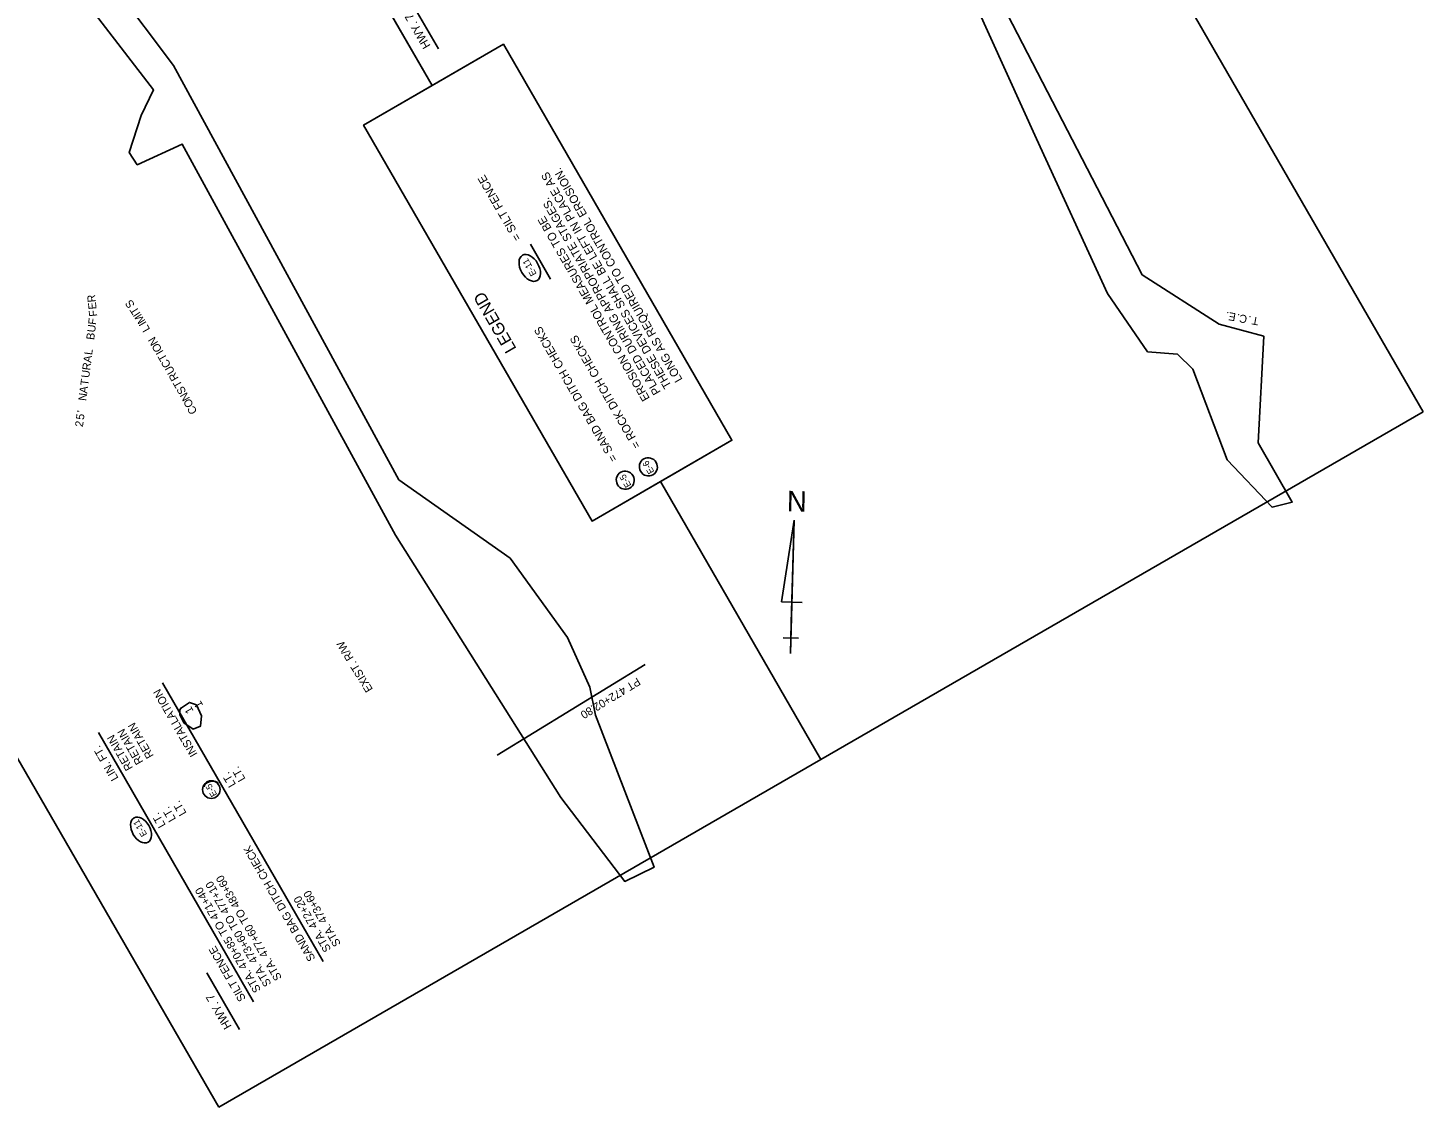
# Model space of a CAD drawing. Extents: x 956270 to 957915, y 1920520 to 1922423.
# Drawn here: x 956869 to 957915, y 1920520 to 1921329 of the extents above; entities that cross this region are included whole.
import ezdxf

# ---------------------------------------------------------------- set-up
doc = ezdxf.new("R2010")
doc.units = 0
for name, color, linetype in [('1', 7, 'Continuous'), ('44', 7, 'Continuous'), ('63', 7, 'Continuous'), ('Level 1', 7, 'Continuous'), ('Level 44', 7, 'Continuous'), ('NO PLOT', 7, 'Continuous'), ('R_Draft', 7, 'Continuous'), ('R_Horz Alg Annot', 7, 'Continuous'), ('S_TREE', 7, 'Continuous')]:
    doc.layers.add(name, color=color, linetype=linetype)

msp = doc.modelspace()

# ---------------------------------------------------------------- linework, layer by layer
at = {"layer": '1'}
for p, q in [((957172.3, 1921286.1), (957029.2, 1921533.9)), ((957225.7, 1921317), (957120.9, 1921256.4)), ((957292.2, 1920959.7), (957120.9, 1921256.4)), ((957367.7, 1921003.2), (957292.2, 1920959.7)), ((957463.8, 1920781), (957343.6, 1920989.3))]:
    msp.add_line(p, q, dxfattribs=at)
msp.add_lwpolyline([(957367.7, 1921003.2), (957397.1, 1921020.2), (957225.7, 1921317)], dxfattribs=at)
msp.add_circle((957006.8, 1920758.4), 6.61, dxfattribs=at)
msp.add_ellipse((956954.1, 1920728.1), major_axis=(-5.26, 9.11), ratio=0.638788, dxfattribs=at)
at = {"layer": '44'}
for p, q in [((957177, 1921313.6), (957152.6, 1921355.9)), ((957090.6, 1920629.6), (956970.1, 1920838.3)), ((957038.5, 1920599.4), (956922.1, 1920801.1)), ((957027.9, 1920578.7), (957003.5, 1920621))]:
    msp.add_line(p, q, dxfattribs=at)
at = {"layer": '63'}
for p, q in [((957443.6, 1920960.4), (957434.3, 1920899.1)), ((957440.9, 1920860.4), (957443.6, 1920960.4)), ((957443.6, 1920960.4), (957441.5, 1920883.5)), ((957434.3, 1920899.1), (957449.6, 1920898.7)), ((957440.9, 1920860.4), (957441.5, 1920883.5)), ((957441.2, 1920872), (957435.5, 1920872.1)), ((957435.5, 1920872.1), (957447, 1920871.8)), ((957440.9, 1920860.4), (957441.2, 1920872))]:
    msp.add_line(p, q, dxfattribs=at)
at = {"layer": 'Level 1'}
for centre, major_axis, ratio in [((957245.5, 1921149.4), (-5.48, 9.49), 0.622952), ((957334.4, 1921000.3), (3.44, -5.96), 0.97521), ((957317.1, 1920990.3), (3.44, -5.96), 0.97521)]:
    msp.add_ellipse(centre, major_axis=major_axis, ratio=ratio, dxfattribs=at)
at = {"layer": 'Level 44'}
msp.add_lwpolyline([(957261.1, 1921141), (957246, 1921167.1)], dxfattribs=at)
at = {"layer": 'NO PLOT'}
for points in [[(957915.2, 1921041.6), (957117.5, 1922423.2), (956666.2, 1922162.6), (956816.7, 1921902), (956875.1, 1921935.7), (957087.6, 1921567.7), (957029.2, 1921533.9), (957172.3, 1921286.1), (957225.7, 1921317), (957397.1, 1921020.2), (957343.6, 1920989.3), (957463.8, 1920781)], [(957915.2, 1921041.6), (957117.5, 1922423.2), (956666.2, 1922162.6), (956816.7, 1921902), (956875.1, 1921935.7), (957087.6, 1921567.7), (957029.2, 1921533.9), (957172.3, 1921286.1), (957225.7, 1921317), (957397.1, 1921020.2), (957343.6, 1920989.3), (957463.8, 1920781)], [(957915.2, 1921041.6), (957117.5, 1922423.2), (956666.2, 1922162.6), (956816.7, 1921902), (956875.1, 1921935.7), (957087.6, 1921567.7), (957029.2, 1921533.9), (957172.3, 1921286.1), (957225.7, 1921317), (957397.1, 1921020.2), (957343.6, 1920989.3), (957463.8, 1920781)], [(957915.2, 1921041.6), (957117.5, 1922423.2), (956666.2, 1922162.6), (956816.7, 1921902), (956875.1, 1921935.7), (957087.6, 1921567.7), (957029.2, 1921533.9), (957172.3, 1921286.1), (957225.7, 1921317), (957397.1, 1921020.2), (957343.6, 1920989.3), (957463.8, 1920781)], [(957012.5, 1920520.4), (956420.5, 1921545.9), (956463.3, 1921570.6), (956365.4, 1921740.1), (956378, 1921747.4), (956270.3, 1921934.1), (956666.2, 1922162.6), (956816.7, 1921902), (956750, 1921863.5), (956962.5, 1921495.4), (957029.2, 1921533.9), (957172.3, 1921286.1), (957120.9, 1921256.4), (957292.2, 1920959.7), (957343.6, 1920989.3), (957463.8, 1920781)], [(957012.5, 1920520.4), (956420.5, 1921545.9), (956463.3, 1921570.6), (956365.4, 1921740.1), (956378, 1921747.4), (956270.3, 1921934.1), (956666.2, 1922162.6), (956816.7, 1921902), (956750, 1921863.5), (956962.5, 1921495.4), (957029.2, 1921533.9), (957172.3, 1921286.1), (957120.9, 1921256.4), (957292.2, 1920959.7), (957343.6, 1920989.3), (957463.8, 1920781)], [(957012.5, 1920520.4), (956420.5, 1921545.9), (956463.3, 1921570.6), (956365.4, 1921740.1), (956378, 1921747.4), (956270.3, 1921934.1), (956666.2, 1922162.6), (956816.7, 1921902), (956750, 1921863.5), (956962.5, 1921495.4), (957029.2, 1921533.9), (957172.3, 1921286.1), (957120.9, 1921256.4), (957292.2, 1920959.7), (957343.6, 1920989.3), (957463.8, 1920781)], [(957012.5, 1920520.4), (956420.5, 1921545.9), (956463.3, 1921570.6), (956365.4, 1921740.1), (956378, 1921747.4), (956270.3, 1921934.1), (956666.2, 1922162.6), (956816.7, 1921902), (956750, 1921863.5), (956962.5, 1921495.4), (957029.2, 1921533.9), (957172.3, 1921286.1), (957120.9, 1921256.4), (957292.2, 1920959.7), (957343.6, 1920989.3), (957463.8, 1920781)]]:
    msp.add_lwpolyline(points, close=True, dxfattribs=at)
for points in [[(956883.9, 1921386.2), (956963.4, 1921282.8), (956954.1, 1921263.6), (956945.3, 1921236), (956951.3, 1921226.7), (956985, 1921242.2), (957144.9, 1920949.1), (957268.7, 1920752.5), (957316.7, 1920689.6), (957338.7, 1920700.2), (957294.8, 1920814.2), (957290.6, 1920835.1), (957273.8, 1920872.4), (957230.9, 1920931.8), (957147.3, 1920990.6), (956978.4, 1921301), (956892, 1921416.3)], [(957580.2, 1921345.8), (957625.4, 1921246.1), (957678.5, 1921130.2), (957708.7, 1921086.5), (957731, 1921084.7), (957742.6, 1921073.5), (957768.3, 1921005.6), (957802, 1920970), (957817.1, 1920973.9), (957791.5, 1921018.4), (957795.7, 1921098.2), (957762.4, 1921107.2), (957704.5, 1921144.2), (957596.2, 1921354.1)]]:
    msp.add_lwpolyline(points, dxfattribs=at)
at = {"layer": 'R_Horz Alg Annot'}
msp.add_lwpolyline([(957221.1, 1920784.2), (957332, 1920852.1)], dxfattribs=at)
at = {"layer": 'S_TREE'}
msp.add_lwpolyline([(956983.6, 1920819.1), (956990.4, 1920823.8), (956995.6, 1920821.9), (956999.3, 1920813.6), (956998.7, 1920806), (956993.3, 1920803.8), (956986.3, 1920808.5), (956983.3, 1920814.5), (956983.3, 1920818.2), (956984.2, 1920819.6)], dxfattribs=at)
msp.add_ellipse((957006.6, 1920761.7), major_axis=(-5.2, -1.23), ratio=0.540699, start_param=3.141593, end_param=6.283185, dxfattribs=at)

# ---------------------------------------------------------------- texts
at = {"layer": '1'}
for s, p in [('E-5 ', (957011.3, 1920754.7)), ('E-11', (956958.8, 1920724.8))]:
    msp.add_text(s, height=4.8, rotation=120, dxfattribs=at).set_placement(p)
at = {"layer": '44'}
for s, height, p in [('HWY. 7', 6.25, (957171.3, 1921315.9)), ('INSTALLATION', 6, (956996.6, 1920785)), ('1', 6, (956993.7, 1920817.4)), ('1', 6, (957000.9, 1920821.6)), ('RETAIN', 6, (956963.8, 1920783.8)), ('RETAIN', 6, (956948.2, 1920774.7)), ('RETAIN', 6, (956955.9, 1920779.2)), ('LIN. FT.', 6, (956937.4, 1920767)), ('LT.', 6, (957032.6, 1920766.4)), ('LT.', 6, (957025.4, 1920762.2)), ('LT.', 6, (956980.5, 1920736.3)), ('LT.', 6, (956988.4, 1920740.8)), ('LT.', 6, (956972.8, 1920731.8)), ('SAND BAG DITCH CHECK', 6, (957085, 1920631.8)), ('STA. 477+60 TO 483+60', 6, (957059.9, 1920617.3)), ('STA. 470+85 TO 471+40', 6, (957044.2, 1920608.3)), ('STA. 473+60 TO 477+10', 6, (957052, 1920612.8)), ('STA. 473+60', 6, (957104.1, 1920642.8)), ('STA. 472+20', 6, (957096.8, 1920638.7)), ('SILT FENCE      ', 6, (957032.9, 1920601.7)), ('HWY. 7', 6.25, (957022.2, 1920581))]:
    msp.add_text(s, height=height, rotation=120, dxfattribs=at).set_placement(p)
at = {"layer": '63'}
msp.add_text('N', height=15.4, rotation=358.5016, dxfattribs=at).set_placement((957438.1, 1920967))
at = {"layer": 'Level 1'}
for s, height, p in [('= SILT FENCE', 6.25, (957239.3, 1921171.7)), ('THESE DEVICES SHALL BE LEFT IN PLACE AS ', 6.25, (957352, 1921061.1)), ('LONG AS REQUIRED TO CONTROL EROSION.', 6.25, (957360.2, 1921065.8)), ('PLACED DURING APPROPRIATE STAGES. ', 6.25, (957343.9, 1921056.4)), ('EROSION CONTROL MEASURES TO BE', 6.25, (957335.7, 1921051.7)), ('E-11 ', 4.88, (957250.8, 1921145)), ('= SAND BAG DITCH CHECKS', 6.25, (957311.5, 1921006.2)), ('= ROCK DITCH CHECKS', 6.25, (957328.8, 1921016.2)), ('E-5 ', 4.88, (957321.8, 1920986.5)), ('E-6 ', 4.88, (957339, 1920996.7))]:
    msp.add_text(s, height=height, rotation=120, dxfattribs=at).set_placement(p)
at = {"layer": 'Level 44'}
msp.add_text('LEGEND', height=9.14, rotation=120, dxfattribs=at).set_placement((957235.8, 1921088.9))
at = {"layer": 'R_Draft'}
for s, rotation, p in [('R', 95.8222, (956920.2, 1921123.9)), ('E', 95.8222, (956920.8, 1921118.6)), ('S', 124.9766, (956949.7, 1921121.8)), ('F', 82.6936, (956920.3, 1921106.5)), ('F', 95.8222, (956921.3, 1921113.2)), ('T', 122.7559, (956953, 1921116.9)), ('I', 122.7559, (956954, 1921115.3)), ('M', 122.7559, (956957.5, 1921109.9)), ('.', 169.8911, (957769.9, 1921116.2)), ('E', 169.8911, (957775.2, 1921115.3)), ('.', 169.8911, (957778.1, 1921114.7)), ('C', 169.8911, (957783.7, 1921113.7)), ('.', 169.8911, (957786.6, 1921113.2)), ('T', 169.8911, (957792.3, 1921112.2)), ('B', 82.6936, (956918.9, 1921095.2)), ('U', 82.6936, (956919.6, 1921100.8)), ('I', 120.1562, (956958.4, 1921108.1)), ('L', 120.1562, (956961.1, 1921103.4)), ('N', 120.781, (956967.1, 1921093.4)), ('O', 120.3645, (956970.1, 1921088.3)), ('A', 82.6936, (956916.7, 1921078.1)), ('L', 82.6936, (956917.4, 1921083.9)), ('I', 120.3645, (956971.1, 1921086.6)), ('T', 119.9843, (956974, 1921081.6)), ('C', 119.9843, (956976.8, 1921076.6)), ('U', 82.6936, (956915.2, 1921066.7)), ('R', 82.6936, (956915.9, 1921072.4)), ('U', 119.9275, (956979.7, 1921071.7)), ('R', 119.9275, (956982.5, 1921066.7)), ('A', 82.6936, (956913.7, 1921055.1)), ('T', 82.6936, (956914.5, 1921060.9)), ('T', 119.5062, (956985.4, 1921061.6)), ('S', 119.3032, (956988.2, 1921056.7)), ('N', 82.6936, (956913, 1921049.5)), ('N', 119.3032, (956991, 1921051.7)), ('O', 118.0335, (956993.7, 1921046.6)), ('5', 82.6936, (956911.2, 1921035.3)), ("'", 82.6936, (956911.9, 1921040.6)), ('C', 118.0335, (956996.4, 1921041.6)), ('2', 82.6936, (956910.5, 1921029.9)), ('EXIST. R/W', 121.503, (957128.1, 1920833.6))]:
    msp.add_text(s, height=6, rotation=rotation, dxfattribs=at).set_placement(p)
at = {"layer": 'R_Horz Alg Annot'}
msp.add_text('PT 472+02.80', height=6, rotation=211.4607, dxfattribs=at).set_placement((957326.1, 1920842.6))

doc.saveas('drawing.dxf')
